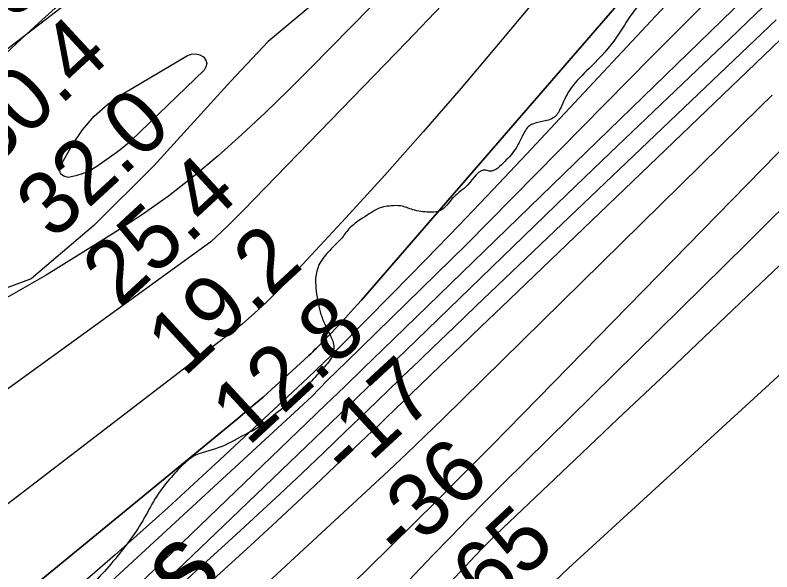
# Model space of a CAD drawing. Extents: x 3361039 to 3398939, y 576572 to 602007.
# Drawn here: x 3383096 to 3383897, y 596060 to 596649 of the extents above; entities that cross this region are included whole.
import ezdxf

# ---------------------------------------------------------------- set-up
doc = ezdxf.new("R2010")
doc.units = 0
for name, color, linetype in [('V-RIVR-EDGE', 7, 'Continuous'), ('V-RIVR-IDEN', 7, 'Continuous'), ('V-RIVR-RANG', 7, 'Continuous'), ('V-SITE-VEGE', 7, 'Continuous'), ('V-TOPO-DPTH', 7, 'Continuous'), ('V-TOPO-MAJR', 7, 'Continuous'), ('V-TOPO-MINR', 7, 'Continuous'), ('V-TOPO-WATR', 7, 'Continuous')]:
    doc.layers.add(name, color=color, linetype=linetype)

msp = doc.modelspace()

# ---------------------------------------------------------------- linework, layer by layer
at = {"layer": 'V-RIVR-EDGE'}
msp.add_spline([(3385319.86, 599617.15), (3385311.39, 599591.95), (3385309.54, 599580.62), (3385310.59, 599561.97), (3385309.8, 599540.04), (3385308.68, 599529.81), (3385307.52, 599501.66), (3385304.54, 599481.93), (3385297.17, 599457.09), (3385296.76, 599438.82), (3385298.14, 599405.91), (3385297.68, 599368.63), (3385295.77, 599332.81), (3385287.26, 599291.52), (3385284.63, 599264.11), (3385282.72, 599231.95), (3385283.32, 599178.94), (3385278.73, 599095.25), (3385275.01, 599070.76), (3385273.84, 599040.43), (3385273.03, 599006.07), (3385269.62, 598960.75), (3385265.86, 598917.99), (3385263.63, 598902.64), (3385261.39, 598885.1), (3385260.29, 598881.08), (3385260.27, 598873.4), (3385266.07, 598855.48), (3385266.05, 598847.07), (3385265.66, 598835.74), (3385265.62, 598820.02), (3385266.69, 598810.15), (3385270.68, 598798.07), (3385270.66, 598787.11), (3385270.21, 598755.31), (3385266.83, 598719.86), (3385263.83, 598689.16), (3385264.17, 598678.19), (3385267.07, 598668.68), (3385269.62, 598665.38), (3385269.61, 598659.53), (3385260.07, 598643.47), (3385251.63, 598631.8), (3385249.4, 598618.64), (3385248.27, 598602.93), (3385245.65, 598579.9), (3385243.81, 598574.42), (3385238.3, 598564.93), (3385233.54, 598559.1), (3385232.43, 598554.35), (3385230.94, 598543.02), (3385228.32, 598518.17), (3385228.63, 598496.97), (3385228.23, 598484.17), (3385221.26, 598470.3), (3385216.12, 598462.64), (3385209.51, 598451.32), (3385204, 598441.46), (3385200.7, 598435.99), (3385196.66, 598426.86), (3385194.08, 598419.56), (3385195.47, 598392.5), (3385191.41, 598375.7), (3385185.53, 598362.19), (3385174.52, 598344.3), (3385170.86, 598341.02), (3385151.07, 598321.69), (3385142.28, 598314.41), (3385135.68, 598306.75), (3385131.27, 598296.16), (3385129.05, 598288.12), (3385126.47, 598277.89), (3385127.53, 598264.36), (3385129.31, 598245.71), (3385125.6, 598223.79), (3385121.16, 598200.41), (3385126.63, 598197.1), (3385126.62, 598193.08), (3385120.36, 598174.82), (3385117.8, 598173.73), (3385103.9, 598168.28), (3385087.43, 598162.11), (3385067.66, 598146.44), (3385054.45, 598126.36), (3385045.25, 598101.53), (3385041.89, 598073.76), (3385035.63, 598055.13), (3385018.38, 598028.12), (3385003.34, 598008.42), (3384987.56, 597982.14), (3384972.52, 597960.61), (3384967.01, 597952.21), (3384958.55, 597929.94), (3384948.63, 597908.39), (3384939.08, 597890.87), (3384932.49, 597887.96), (3384925.16, 597879.21), (3384919.66, 597871.55), (3384916.34, 597859.12), (3384911.12, 597818.56), (3384903.77, 597803.96), (3384893.15, 597793.38), (3384877.04, 597782.82), (3384864.22, 597774.45), (3384852.5, 597763.14), (3384846.64, 597759.87), (3384841.87, 597754.4), (3384836.75, 597752.22), (3384831.26, 597751.13), (3384825.42, 597751.15), (3384821.02, 597748.96), (3384808.57, 597737.3), (3384797.56, 597723.07), (3384783.29, 597717.62), (3384768.67, 597716.56), (3384763.55, 597714.38), (3384758.06, 597711.47), (3384756.58, 597707.45), (3384756.57, 597700.14), (3384757.98, 597681.86), (3384759.43, 597674.91), (3384767.08, 597666.85), (3384767.8, 597662.1), (3384764.11, 597648.21), (3384754.94, 597633.61), (3384742.47, 597618.29), (3384735.15, 597613.56), (3384730.03, 597611.01), (3384722.72, 597611.03), (3384718.33, 597611.41), (3384713.57, 597609.96), (3384708.45, 597607.41), (3384700.76, 597602.68), (3384682.45, 597588.83), (3384665.26, 597583.39), (3384655.38, 597579.76), (3384649.52, 597574.66), (3384639.98, 597561.89), (3384632.63, 597546.55), (3384628.58, 597534.5), (3384628.92, 597525.72), (3384632.93, 597520.96), (3384635.47, 597511.82), (3384635.46, 597506.33), (3384632.16, 597502.69), (3384610.17, 597481.9), (3384595.14, 597464.76), (3384587.81, 597457.83), (3384578.65, 597445.43), (3384573.51, 597437.76), (3384572.03, 597431.55), (3384572.02, 597425.34), (3384577.46, 597411.43), (3384577.45, 597406.32), (3384568.63, 597387.33), (3384559.44, 597366.52), (3384558.34, 597365.42), (3384549.56, 597362.52), (3384541.15, 597358.88), (3384528.33, 597350.87), (3384500.11, 597319.87), (3384474.46, 597295.08), (3384441.5, 597273.59), (3384418.07, 597259.03), (3384397.58, 597248.11), (3384366.82, 597225.89), (3384340.8, 597201.83), (3384306.01, 597173.77), (3384286.58, 597152.98), (3384263.48, 597126.35), (3384241.84, 597096.06), (3384215.09, 597069.81), (3384190.92, 597052.69), (3384183.61, 597050.51), (3384172.27, 597049.81), (3384159.85, 597052.04), (3384147.8, 597056.09), (3384140.85, 597056.83), (3384133.18, 597056.49), (3384126.59, 597053.58), (3384115.61, 597048.12), (3384093.62, 597026.61), (3384081.16, 597014.21), (3384070.52, 596998.52), (3384058.39, 596970.04), (3384050.65, 596943.37), (3384045.12, 596924.74), (3384039.6, 596909.77), (3384031.17, 596902.11), (3384022.38, 596896.29), (3384002.63, 596888.66), (3383996.41, 596886.85), (3383978.08, 596865.69), (3383967.8, 596848.9), (3383957.89, 596831.01), (3383942.86, 596814.6), (3383926.37, 596800.38), (3383906.6, 596785.81), (3383874.35, 596755.55), (3383858.96, 596737.68), (3383839.52, 596713.23), (3383821.19, 596692.08), (3383808.37, 596681.87), (3383788.98, 596672.05), (3383779.83, 596671.34), (3383773.61, 596669.16), (3383762.27, 596664.81), (3383749.45, 596651.68), (3383732.57, 596626.13), (3383706.17, 596595.49), (3383686.38, 596574.7), (3383681.61, 596567.77), (3383672.43, 596549.15), (3383669.49, 596544.04), (3383657.04, 596537.49), (3383644.61, 596534.6), (3383640.58, 596532.41), (3383632.88, 596521.1), (3383623.7, 596505.04), (3383610.87, 596491.18), (3383602.45, 596484.99), (3383599.16, 596484.26), (3383594.41, 596485.37), (3383574.99, 596469.7), (3383560.34, 596456.94), (3383544.59, 596441.99), (3383533.98, 596440.92), (3383517.17, 596443.52), (3383504.02, 596447.58), (3383494.15, 596447.6), (3383486.11, 596446.53), (3383468.91, 596437.79), (3383449.5, 596423.22), (3383441.06, 596412.64), (3383427.5, 596398.78), (3383422, 596391.85), (3383417.6, 596385.28), (3383416.13, 596380.53), (3383414.28, 596373.23), (3383414.26, 596363.72), (3383418.21, 596338.49), (3383422.21, 596326.42), (3383429.48, 596311.05), (3383433.47, 596299.7), (3383431.98, 596289.11), (3383422.08, 596275.97), (3383408.15, 596260.29), (3383387.63, 596240.23), (3383367.12, 596223.83), (3383352.47, 596212.54), (3383337.46, 596204.53), (3383311.84, 596191.8), (3383284.04, 596182), (3383274.15, 596173.98), (3383259.49, 596158.3), (3383244.45, 596137.87), (3383231.23, 596114.51), (3383201.89, 596074), (3383183.56, 596053.21), (3383176.59, 596045.92), (3383169.63, 596037.16), (3383154.96, 596017.82), (3383136.61, 595991.18), (3383123.42, 595975.13), (3383109.14, 595966.03), (3383090.1, 595956.57), (3383070.72, 595951.14), (3383044.39, 595947.18), (3383011.84, 595942.14), (3382982.59, 595939.29), (3382960.64, 595934.23), (3382941.62, 595928.06), (3382928.81, 595919.69), (3382906.1, 595901.83), (3382880.1, 595885.81), (3382857.4, 595868.32), (3382833.23, 595852.29), (3382824.44, 595844.64), (3382818.2, 595833.69), (3382810.14, 595827.13), (3382799.89, 595821.31), (3382776.11, 595812.23), (3382746.08, 595790.37), (3382726.29, 595771.77), (3382717.85, 595757.9), (3382716.37, 595752.42), (3382716.35, 595740.73), (3382715.58, 595726.11), (3382711.89, 595711.49), (3382701.96, 595688.12), (3382682.89, 595664.41), (3382657.61, 595639.98), (3382621.72, 595611.92), (3382590.94, 595585.31), (3382557.62, 595562), (3382515.51, 595531.4), (3382468.28, 595501.9), (3382399.07, 595451.63), (3382354.76, 595420.3), (3382329.85, 595402.09), (3382312.28, 595391.53), (3382279.35, 595376.99), (3382250.06, 595361.71), (3382227.75, 595354.82), (3382194.09, 595344.3), (3382150.18, 595326.5), (3382116.16, 595314.88), (3382080.66, 595299.25), (3382061.26, 595288.33), (3382039.67, 595281.08), (3382015.9, 595274.56), (3381988.82, 595263.66), (3381924.8, 595242.25), (3381888.21, 595229.54), (3381851.64, 595223.78), (3381811.79, 595222.79), (3381786.93, 595221.02), (3381761.33, 595213.77), (3381741.93, 595206.14), (3381717.04, 595193.05), (3381692.87, 595175.19), (3381667.97, 595156.98), (3381621.11, 595130.04), (3381567.31, 595103.13), (3381511.32, 595078.41), (3381469.97, 595060.6), (3381438.13, 595044.23), (3381400.81, 595031.52), (3381367.52, 595022.47), (3381328.03, 595016.35), (3381309.02, 595017.13), (3381273.58, 595022.33), (3381264.44, 595022.36), (3381246.52, 595019.48), (3381219.45, 595012.23), (3381174.48, 595010.88), (3381152.92, 595011.67), (3381127.69, 595010.63), (3381092.59, 595005.97), (3381064.44, 595003.48), (3381034.8, 594994.05), (3381008.82, 594981.32), (3380980.63, 594964.57), (3380946.57, 594940.89), (3380922.03, 594921.22), (3380915.8, 594913.55), (3380913.22, 594905.88), (3380904.43, 594898.96), (3380882.83, 594884.39), (3380865.62, 594873.83), (3380856.48, 594871.3), (3380842.94, 594868.41), (3380834.89, 594864.04), (3380818.77, 594848.36), (3380800.46, 594836.34), (3380772.28, 594821.43), (3380760.93, 594817.07), (3380757.27, 594813.06), (3380750.68, 594808.32), (3380738.23, 594802.14), (3380723.6, 594798.88), (3380707.16, 594800.38), (3380694.73, 594802.24), (3380689.62, 594805.18), (3380685.26, 594813.6), (3380685.27, 594820.54), (3380683.83, 594829.69), (3380676.2, 594844.69), (3380655.78, 594865.21), (3380634.98, 594880.62), (3380615.26, 594889.44), (3380601.01, 594894.23), (3380590.78, 594893.16), (3380583.47, 594895.37), (3380575.81, 594899.77), (3380572.16, 594902.34), (3380566.32, 594907.47), (3380560.09, 594900.54), (3380548.73, 594890.7), (3380542.5, 594883.77), (3380535.89, 594871.72), (3380534.04, 594860.4), (3380532.56, 594853.46), (3380527.41, 594843.96), (3380512.75, 594827.19), (3380501.02, 594811.86), (3380491.1, 594793.61), (3380468.36, 594761.13), (3380453.69, 594741.06), (3380439.04, 594729.77), (3380420, 594719.94), (3380389.99, 594704.66), (3380353.4, 594689.04), (3380320.11, 594680.71), (3380292.66, 594665.06), (3380267.77, 594652.33), (3380251.3, 594646.15), (3380229.71, 594635.61), (3380197.13, 594617.41), (3380178.83, 594608.68), (3380146.63, 594596.7), (3380094.32, 594580.74), (3380046.39, 594564.41), (3380003.58, 594547.34), (3379965.9, 594536.83), (3379941.4, 594531.41), (3379928.97, 594529.98), (3379910.31, 594526), (3379887.27, 594519.48), (3379863.14, 594517.34), (3379841.92, 594512.64), (3379826.55, 594505.37), (3379800.92, 594489.35), (3379772.01, 594474.07), (3379738.35, 594464.28), (3379722.62, 594458.84), (3379694.08, 594446.48), (3379674.68, 594438.85), (3379654.94, 594434.88), (3379623.86, 594432.03), (3379592.04, 594427.36), (3379570.47, 594423.76), (3379542.66, 594414.69), (3379515.96, 594407.44), (3379503.51, 594401.26), (3379489.97, 594395.08), (3379466.93, 594388.55), (3379430.71, 594377.31), (3379379.12, 594357.7), (3379353.14, 594348.26), (3379334.85, 594343.55), (3379316.19, 594335.92), (3379302.28, 594329.01), (3379279.22, 594316.27), (3379263.85, 594306.44), (3379246.65, 594300.27), (3379225.06, 594290.82), (3379184.8, 594269.72), (3379153.33, 594255.9), (3379134.65, 594244.62), (3379112.32, 594230.05), (3379083.75, 594208.55), (3379059.6, 594196.19), (3379026.66, 594179.09), (3379000.68, 594170.38), (3378975.43, 594159.84), (3378928.93, 594130.34), (3378879.51, 594101.22), (3378845.83, 594079.01), (3378832.64, 594069.17), (3378785.43, 594044.8), (3378733.45, 594018.24), (3378688.06, 593992.4), (3378659.89, 593980.77), (3378638.65, 593968.39), (3378601.3, 593940.7), (3378552.59, 593903.54), (3378520.01, 593884.24), (3378468.39, 593853.67), (3378415.32, 593828.21), (3378382.75, 593811.84), (3378354.19, 593794), (3378320.86, 593766.3), (3378294.47, 593738.58), (3378277.62, 593725.1), (3378246.16, 593714.21), (3378222.01, 593708.06), (3378198.61, 593704.09), (3378184.71, 593700.84), (3378170.43, 593691.73), (3378149.19, 593676.07), (3378110.36, 593643.63), (3378072.65, 593618.5), (3378039.32, 593594.46), (3377997.95, 593566.78), (3377967.92, 593544.92), (3377933.49, 593516.13), (3377904.2, 593497.19), (3377862.83, 593473.9), (3377818.54, 593450.61), (3377791.08, 593430.94), (3377768.73, 593412.72), (3377749.67, 593388.64), (3377728.03, 593361.64), (3377695.07, 593334.31), (3377661.36, 593305.88), (3377617.78, 593271.26), (3377586.63, 593241.72), (3377549.65, 593215.13), (3377484.1, 593167.77), (3377437.59, 593133.53), (3377406.08, 593106.19), (3377382.27, 593085.04), (3377318.84, 593008.07), (3377284.74, 592967.94), (3377215.47, 592893.91), (3377171.11, 592842.48), (3377138.85, 592804.17), (3377088.65, 592754.95), (3377046.13, 592708.26), (3376960.03, 592629.88), (3376947.21, 592616.39), (3376906.35, 592574.91)], degree=3, dxfattribs=at)
at = {"layer": 'V-SITE-VEGE'}
msp.add_lwpolyline([(3383050.51, 596585.11), (3383157.37, 596667.44), (3383208.04, 596712.55), (3383281.66, 596774.3), (3383300.66, 596778.25), (3383311.74, 596774.29), (3383330.74, 596767.96), (3383337.86, 596764.79), (3383420.19, 596722.83), (3383439.98, 596704.63), (3383440.77, 596691.17), (3383410.69, 596660.3), (3383363.98, 596621.51), (3383324.4, 596579.56), (3383242.86, 596490.11), (3383179.53, 596426.79), (3383113.03, 596370.59), (3383071.08, 596354.76)], dxfattribs=at)
at = {"layer": 'V-TOPO-DPTH'}
for points in [[(3382383.17, 595402.2), (3382699.58, 595621.08), (3382854.82, 595733.08), (3382879.55, 595750.05), (3382894.05, 595759.38), (3382907.7, 595770.42), (3383134.72, 595992.07), (3383410.35, 596245.96), (3383426.57, 596262.95), (3383447.05, 596282.48), (3383573.37, 596406.48), (3383769.69, 596605.22), (3383869.55, 596705.44), (3383881.5, 596719.04), (3383931.01, 596769.15), (3384294.53, 597098.6), (3384387.52, 597175.85), (3384438.7, 597214.88), (3384476.25, 597248.85)], [(3384476.25, 597248.85), (3384438.7, 597214.88), (3384387.52, 597175.85), (3384294.53, 597098.6), (3383931.01, 596769.15), (3383881.5, 596719.04), (3383869.55, 596705.44), (3383769.69, 596605.22), (3383573.37, 596406.48), (3383447.05, 596282.48), (3383426.57, 596262.95), (3383410.35, 596245.96), (3383134.72, 595992.07), (3382907.7, 595770.42), (3382894.05, 595759.38), (3382879.55, 595750.05), (3382854.82, 595733.08), (3382699.58, 595621.08), (3382383.17, 595402.2)], [(3383259.11, 596054.25), (3383325.28, 596117.19), (3383404.28, 596193.11), (3383430.62, 596218.45), (3383456.94, 596243.82), (3383483.23, 596269.21), (3383509.5, 596294.61), (3383634.4, 596415.54), (3383680.07, 596459.64), (3383725.82, 596503.65), (3383771.69, 596547.55), (3383817.64, 596591.36), (3383852.05, 596624.08), (3383880.88, 596651.43), (3383909.77, 596678.73), (3383938.72, 596705.96), (3383967.72, 596733.14), (3384288.52, 597032.99), (3384325.82, 597068.36), (3384362.77, 597104.09), (3384399.2, 597140.36), (3384435.28, 597176.97), (3384495.49, 597238.97), (3384501.13, 597244.93)], [(3384501.13, 597244.93), (3384495.49, 597238.97), (3384435.28, 597176.97), (3384399.2, 597140.36), (3384362.77, 597104.09), (3384325.82, 597068.36), (3384288.52, 597032.99), (3383967.72, 596733.14), (3383938.72, 596705.96), (3383909.77, 596678.73), (3383880.88, 596651.43), (3383852.05, 596624.08), (3383817.64, 596591.36), (3383771.69, 596547.55), (3383725.82, 596503.65), (3383680.07, 596459.64), (3383634.4, 596415.54), (3383509.5, 596294.61), (3383483.23, 596269.21), (3383456.94, 596243.82), (3383430.62, 596218.45), (3383404.28, 596193.11), (3383325.28, 596117.19), (3383259.11, 596054.25)], [(3382844.45, 595823.15), (3383331.41, 596222.43), (3383345.05, 596233.81), (3383358.56, 596245.35), (3383371.86, 596257.11), (3383385.03, 596269.04), (3383406.93, 596289.2), (3383409.04, 596291.17), (3383411.12, 596293.16), (3383413.18, 596295.19), (3383415.21, 596297.24), (3383428.72, 596311.06), (3383437.41, 596320.11), (3383445.99, 596329.27), (3383454.4, 596338.58), (3383462.7, 596347.99), (3383757.91, 596688.88)], [(3383905.92, 596623.14), (3383610.84, 596340.43), (3383589.35, 596319.84), (3383567.88, 596299.23), (3383546.42, 596278.62), (3383524.97, 596257.99), (3383489.28, 596223.66), (3383485.68, 596220.2), (3383482.07, 596216.75), (3383478.45, 596213.31), (3383474.83, 596209.87), (3383427.52, 596165.11), (3383400.17, 596139.38), (3383372.72, 596113.75), (3383345.12, 596088.29), (3383317.42, 596062.92), (3382962.92, 595740.18)], [(3383905.92, 596623.14), (3383610.84, 596340.43), (3383589.35, 596319.84), (3383567.88, 596299.23), (3383546.42, 596278.62), (3383524.97, 596257.99), (3383489.28, 596223.66), (3383485.68, 596220.2), (3383482.07, 596216.75), (3383478.45, 596213.31), (3383474.83, 596209.87), (3383427.52, 596165.11), (3383400.17, 596139.38), (3383372.72, 596113.75), (3383345.12, 596088.29), (3383317.42, 596062.92), (3382962.92, 595740.18)], [(3383047.05, 595756.61), (3383472.45, 596149.73), (3383491.7, 596167.69), (3383510.84, 596185.76), (3383529.82, 596204), (3383548.68, 596222.36), (3383884.72, 596552.37), (3383897.41, 596564.82)], [(3383897.41, 596564.82), (3383884.72, 596552.37), (3383548.68, 596222.36), (3383529.82, 596204), (3383510.84, 596185.76), (3383491.7, 596167.69), (3383472.45, 596149.73), (3383047.05, 595756.61)], [(3383429.26, 596024.38), (3383469.66, 596063.95), (3383543.01, 596136.25), (3383546.61, 596139.81), (3383550.2, 596143.37), (3383553.77, 596146.95), (3383557.34, 596150.54), (3383583.59, 596177), (3383600.26, 596193.83), (3383616.9, 596210.7), (3383633.51, 596227.59), (3383650.1, 596244.51), (3383965.7, 596567.09)], [(3383965.7, 596567.09), (3383650.1, 596244.51), (3383633.51, 596227.59), (3383616.9, 596210.7), (3383600.26, 596193.83), (3383583.59, 596177), (3383557.34, 596150.54), (3383553.77, 596146.95), (3383550.2, 596143.37), (3383546.61, 596139.81), (3383543.01, 596136.25), (3383469.66, 596063.95), (3383429.26, 596024.38)]]:
    msp.add_lwpolyline(points, dxfattribs=at)
at = {"layer": 'V-TOPO-MAJR'}
for points in [[(3384140.29, 597455.68), (3383716.21, 596907.47), (3383708.37, 596898.9), (3383700.45, 596890.39), (3383692.43, 596881.98), (3383684.33, 596873.64), (3383409.14, 596593.6), (3383385.17, 596569.72), (3383360.86, 596546.2), (3383336.06, 596523.2), (3383310.93, 596500.55), (3383285.03, 596478.85), (3383258.47, 596458.06), (3383230.89, 596438.62), (3383202.64, 596420.09), (3383128.91, 596374.34), (3383062.04, 596336.34)], [(3383085.91, 596608.54), (3383103.2, 596624.86), (3383120.76, 596640.88), (3383138.5, 596656.7), (3383307.75, 596805.14), (3383350.56, 596842.34), (3383393.59, 596879.28), (3383436.95, 596915.83), (3383480.53, 596952.11), (3383541.28, 597002.23), (3383554.41, 597013.52), (3383567.21, 597025.16)], [(3383922.31, 596459.08), (3383896.46, 596433.47), (3383870.57, 596407.9), (3383613.07, 596154.08), (3383594.15, 596135.25), (3383575.36, 596116.3), (3383556.76, 596097.16), (3383538.29, 596077.89), (3383376.93, 595907.99)]]:
    msp.add_lwpolyline(points, dxfattribs=at)
at = {"layer": 'V-TOPO-MINR'}
for points in [[(3384298.8, 597402.94), (3383821.34, 596873.06), (3383797.2, 596845.03), (3383773.17, 596816.92), (3383749.3, 596788.66), (3383725.54, 596760.31), (3383607.77, 596618.95), (3383568.21, 596572.22), (3383528.16, 596525.91), (3383487.38, 596480.25), (3383446.11, 596435.01), (3383386.46, 596370.65), (3383374.45, 596358.12), (3383362.17, 596345.87), (3383349.49, 596334.05), (3383336.53, 596322.5), (3382786.35, 595900.85)], [(3384128.36, 597279.85), (3383959.14, 597098.69), (3383754, 596879.67), (3383743.56, 596868.52), (3383733.14, 596857.35), (3383722.72, 596846.18), (3383712.32, 596834.99), (3383659.53, 596778.18), (3383622.61, 596738.7), (3383585.53, 596699.37), (3383548.19, 596660.29), (3383510.69, 596621.36), (3383337.95, 596443.19), (3383320.77, 596426.1), (3383303.21, 596409.43), (3382720.43, 595987.79), (3382718.08, 595986.38), (3382715.64, 595985.13), (3382713.95, 595984.44), (3382710.49, 595983.15), (3382709.29, 595982.68), (3382708.1, 595982.2), (3382092.52, 595684.52)], [(3384380.32, 597270.17), (3384353.75, 597242.79), (3384327.14, 597215.46), (3384300.47, 597188.19), (3384273.75, 597160.96), (3383895.12, 596776.04), (3383874.86, 596755.29), (3383854.71, 596734.43), (3383834.72, 596713.41), (3383814.84, 596692.29), (3383637.34, 596502.27), (3383602.07, 596464.86), (3383566.6, 596427.65), (3383530.79, 596390.76), (3383494.77, 596354.08), (3383438.06, 596296.84), (3383430.18, 596288.98), (3383422.24, 596281.18), (3383414.21, 596273.48), (3383406.12, 596265.83), (3383312.97, 596178.87), (3383257.84, 596128.27), (3383202.13, 596078.33), (3383145.57, 596029.35)], [(3384495.57, 597253.01), (3384471.58, 597228.38), (3384457.14, 597213.8), (3384442.54, 597199.37), (3384427.72, 597185.17), (3384412.74, 597171.13), (3383917.02, 596713.92), (3383913.7, 596710.87), (3383910.39, 596707.83), (3383907.07, 596704.79), (3383903.74, 596701.75), (3383898.16, 596696.66), (3383896.58, 596695.17), (3383894.82, 596693.44), (3383892.06, 596690.71), (3383484.89, 596295.33), (3383464.96, 596275.99), (3383445, 596256.68), (3383425.01, 596237.39), (3383405, 596218.13), (3383064.75, 595890.96)], [(3384501.13, 597244.93), (3384495.49, 597238.97), (3384435.28, 597176.97), (3384399.2, 597140.36), (3384362.77, 597104.09), (3384325.82, 597068.36), (3384288.52, 597032.99), (3383967.72, 596733.14), (3383938.72, 596705.96), (3383909.77, 596678.73), (3383880.88, 596651.43), (3383852.05, 596624.08), (3383817.64, 596591.36), (3383771.69, 596547.55), (3383725.82, 596503.65), (3383680.07, 596459.64), (3383634.4, 596415.54), (3383509.5, 596294.61), (3383483.23, 596269.21), (3383456.94, 596243.82), (3383430.62, 596218.45), (3383404.28, 596193.11), (3383325.28, 596117.19), (3383259.11, 596054.25)], [(3383757.91, 596688.88), (3383462.7, 596347.99), (3383454.4, 596338.58), (3383445.99, 596329.27), (3383437.41, 596320.11), (3383428.72, 596311.06), (3383415.21, 596297.24), (3383413.18, 596295.19), (3383411.12, 596293.16), (3383409.04, 596291.17), (3383406.93, 596289.2), (3383385.03, 596269.04), (3383371.86, 596257.11), (3383358.56, 596245.35), (3383345.05, 596233.81), (3383331.41, 596222.43), (3382844.45, 595823.15)], [(3383901.57, 596644.32), (3383879.82, 596623.61), (3383606.82, 596363.46), (3383583.76, 596341.45), (3383560.74, 596319.4), (3383537.75, 596297.31), (3383514.8, 596275.19), (3383514.74, 596275.13), (3383491.83, 596253.02), (3383468.9, 596230.93), (3383445.96, 596208.85), (3383423.01, 596186.79), (3383399.96, 596164.83), (3383376.79, 596143), (3383353.44, 596121.37), (3383329.97, 596099.86), (3382936.6, 595742.33)], [(3383905.92, 596623.14), (3383610.84, 596340.43), (3383589.35, 596319.84), (3383567.88, 596299.23), (3383546.42, 596278.62), (3383524.97, 596257.99), (3383489.28, 596223.66), (3383485.68, 596220.2), (3383482.07, 596216.75), (3383478.45, 596213.31), (3383474.83, 596209.87), (3383427.52, 596165.11), (3383400.17, 596139.38), (3383372.72, 596113.75), (3383345.12, 596088.29), (3383317.42, 596062.92), (3382962.92, 595740.18)], [(3383179.88, 596542.59), (3383194.38, 596555.14), (3383210.3, 596566.31), (3383278.61, 596606.59), (3383283, 596608.13), (3383287.31, 596608.59), (3383291.49, 596607.43), (3383295.58, 596605.2), (3383297.88, 596601.8), (3383298.93, 596598.35), (3383298.12, 596594.84), (3383296.08, 596591.28), (3383218.86, 596516.77), (3383214.74, 596512.97), (3383210.5, 596509.32), (3383206.09, 596505.87), (3383201.56, 596502.55), (3383182.59, 596489.35), (3383175.52, 596485.16), (3383168.16, 596481.71), (3383160.39, 596479.36), (3383152.33, 596477.75), (3383147.58, 596479.06), (3383144.37, 596481.4), (3383143.45, 596485.27), (3383144.08, 596490.15), (3383156.53, 596511.87), (3383167.5, 596527.93), (3383179.88, 596542.59)], [(3383897.41, 596564.82), (3383884.72, 596552.37), (3383548.68, 596222.36), (3383529.82, 596204), (3383510.84, 596185.76), (3383491.7, 596167.69), (3383472.45, 596149.73), (3383047.05, 595756.61)], [(3383429.26, 596024.38), (3383469.66, 596063.95), (3383543.01, 596136.25), (3383546.61, 596139.81), (3383550.2, 596143.37), (3383553.77, 596146.95), (3383557.34, 596150.54), (3383583.59, 596177), (3383600.26, 596193.83), (3383616.9, 596210.7), (3383633.51, 596227.59), (3383650.1, 596244.51), (3383965.7, 596567.09)], [(3384035.18, 596508), (3383870.89, 596351.97), (3383825.33, 596308.71), (3383779.76, 596265.45), (3383734.18, 596222.21), (3383688.6, 596178.97), (3383612.3, 596106.61), (3383604.92, 596099.5), (3383597.62, 596092.3), (3383590.45, 596084.99), (3383583.36, 596077.59), (3383539.99, 596031.59)], [(3383932.02, 596293.43), (3383894.38, 596258.92), (3383681.83, 596064.18), (3383666.46, 596049.48)]]:
    msp.add_lwpolyline(points, dxfattribs=at)
at = {"layer": 'V-TOPO-WATR'}
msp.add_lwpolyline([(3382383.17, 595402.2), (3382699.58, 595621.08), (3382854.82, 595733.08), (3382879.55, 595750.05), (3382894.05, 595759.38), (3382907.7, 595770.42), (3383134.72, 595992.07), (3383410.35, 596245.96), (3383426.57, 596262.95), (3383447.05, 596282.48), (3383573.37, 596406.48), (3383769.69, 596605.22), (3383869.55, 596705.44), (3383881.5, 596719.04), (3383931.01, 596769.15), (3384294.53, 597098.6), (3384387.52, 597175.85), (3384438.7, 597214.88), (3384476.25, 597248.85)], dxfattribs=at)

# ---------------------------------------------------------------- texts
at = {"layer": 'V-RIVR-IDEN'}
msp.add_text('Photos', height=83, rotation=46.58259, dxfattribs=at).set_placement((3383080.24, 595807.58))
at = {"layer": 'V-RIVR-RANG'}
for s, rotation, p in [('22.3', 42.72833, (3383002.6, 596558.62)), ('30.4', 42.72833, (3383070.64, 596485.34)), ('32.0', 42.72833, (3383136.54, 596410.08)), ('25.4', 42.72833, (3383206.71, 596338.76)), ('19.2', 42.72833, (3383274.75, 596265.48)), ('12.8', 42.72833, (3383342.79, 596192.19)), ('-17', 42.72833, (3383450.55, 596155.6)), ('-36', 43.01461, (3383506.2, 596070.31)), ('-65', 43.01461, (3383575.78, 595998.46))]:
    msp.add_text(s, height=67, rotation=rotation, dxfattribs=at).set_placement(p)

doc.saveas('drawing.dxf')
